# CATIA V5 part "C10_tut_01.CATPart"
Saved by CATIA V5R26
Part number: Part1
Bounding box of the stored display mesh (mm): x -88.601 to 88.601, y -88.601 to 152.104, z -258.54 to 20
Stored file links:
  D:\_Deepak\CATIA\CATIA V5 2015 Parts Files\Tutorial Files\Tutorials\c10_catia_v5_6r2015_tut\C10_tut_01.CATPart
  J.rX
  E:\ashutosh\Academics\Catia\CATIA V5-6R2013_partfiles\Tutorials\c10_catia_v5-6r2013_tut\c10tut1.CATPart
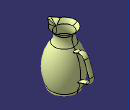
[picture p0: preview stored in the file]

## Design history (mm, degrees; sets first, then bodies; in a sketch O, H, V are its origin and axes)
Body1 (main body)
  Sketch1 on xy-plane, origin (0, 0, 0), H (1, 0, 0), V (0, 1, 0)
    circle A1 centre (0, 0) radius 45
    point P1 (-5, -44.7214)
    point P2 (5, -44.7214)
    radius A1 = 45
    distance P1 P2 = 10
    radius A1 = 45 (reference)
    coincidence: P1 A1
    symmetry: P1 P2 V
  Plane1: type Offset, RefPlane xy-plane, Offset 20
  Sketch2 on Plane1, origin (0, 0, 20), H (1, 0, 0), V (0, 1, 0)
    arc A1 centre (0, 0) radius 60 from (30.5123, -51.6623) to (-30.5123, -51.6623) ccw
    arc A2 centre (0, -75) radius 10 from (-7.9335, -81.0876) to (7.9335, -81.0876) ccw
    point P1 (0, -75)
    line L1 (-7.9335, -81.0876) -> (-30.5123, -51.6623)
    point P2 (-7.9335, -81.0876)
    point P3 (-30.5123, -51.6623)
    point P4 (30.5123, -51.6623)
    point P5 (7.9335, -81.0876)
    line L2 (7.9335, -81.0876) -> (30.5123, -51.6623)
    radius A1 = 60
    radius A2 = 10
    distance O P1 = 75
    angle L1 L2 = 75
    coincidence: P1 V
    tangency: L1 A2
    symmetry: P3 P4 V, P2 P5 V, L1 L2 V
  Line1: type PtPt, FirstPoint vertex [element of Sketch2 | element of Sketch2], SecondPoint Sketch1.P2
  Loft1: Sections (Sketch1.A1; Sketch2), Guides Line1
  Sketch3 on yz-plane, origin (0, 0, 0), H (0, 1, 0), V (0, 0, 1)
    axis line L1 (0, 44.6071) -> (0, -361.7772)
    point P1 (0, 44.6071)
    arc A1 centre (96.9659, -18.0152) radius 55 from (45, 0) to (52.2225, -50) ccw
    point P4 (45, 0)
    point P5 (52.2225, -50)
    arc A2 centre (-106.3983, -163.4215) radius 195 from (52.2225, -50) to (70, -246.5398) cw
    point P7 (70, -246.5398)
    point P8 (54, -258.5398)
    arc A3 centre (0, -425) radius 175 from (54, -258.5398) to (0, -250) ccw
    point P9 (0, -425)
    point P10 (0, -250)
    line L2 (54, -258.5398) -> (64, -258.5398)
    arc A4 centre (64, -251.0398) radius 7.5 from (70, -246.5398) to (64, -258.5398) cw
    radius about axis P4 L1 = 45
    radius A1 = 55
    distance H P5 = 50
    radius A2 = 195
    radius about axis P7 L1 = 70
    distance H P10 = 250
    radius about axis P8 L1 = 54
    radius A3 = 175
    length L2 = 10
    radius A4 = 7.5
    coincidence: P1 V, P4 H, P10 L1, P9 V
    vertical: L1 V
    tangency: A1 A2, A4 L2
    horizontal: L2 H
  Revol1: Element1 Sketch3, Angle1 360
  Sketch4 on yz-plane, origin (0, 0, 0), H (0, 1, 0), V (0, 0, 1)
    point P1 (35.2741, -74.8693)
    line L1 (35.2741, -74.8693) -> (86.9572, -56.0582)
    line L2 (119, -71) -> (145.5066, -143.8262)
    line L3 (130.5647, -175.869) -> (63.8466, -200.1524)
    arc A1 centre (95.5077, -79.5505) radius 25 from (86.9572, -56.0582) to (119, -71) cw
    point P4 (119, -71)
    arc A2 centre (122.0142, -152.3767) radius 25 from (130.5647, -175.869) to (145.5066, -143.8262) ccw
    radius A1 = 25
    radius A2 = 25
    length L1 = 55
    distance H P4 = 71
    angle H L1 = 20
    distance P4 V = 119
    length L2 = 77.5
    length L3 = 71
    perpendicularity: L3 L2, L1 L2
    tangency: A1 L1, A1 L2, A2 L3, A2 L2
  Plane2: type Normal, Curve Sketch4, RefPoint Sketch4.P1, Ratio 0
  Sketch5 on Plane2, origin (0, 7.0853, 2.5788), H (1, 0, 0), V (0, -0.342, 0.9397)
    point P1 (0, -82.1273)
    ellipse A1 centre (0, -82.1273) semi-axes 12.5, 5 rotation 0
    point P2 (0, -87.1273)
    "Radius" A1 = 5
    "Radius" A1 = 12.5
    coincidence: P1 V, P2 V, A1 P2
  Sweep1: type Unspec, Profile Sketch5, Guide Sketch4
  Split1: ToCut Sweep1, Cutting Revol1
